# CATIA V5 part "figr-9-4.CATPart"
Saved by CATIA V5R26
Part number: Part1
Bounding box of the stored display mesh (mm): x -71.324 to 69.61, y -139.735 to 0, z 0 to 45
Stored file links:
  D:\_Deepak\CATIA\CATIA V5-6R2016_Deepak\Resources\Part files\Partfiles\c09_catia_v5_6r2016_prt\figr-9-4.CATPart
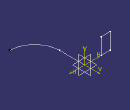
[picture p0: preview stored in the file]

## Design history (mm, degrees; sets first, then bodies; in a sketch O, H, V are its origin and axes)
Body1 (main body)
  Sketch1 on xy-plane, origin (0, 0, 0), H (1, 0, 0), V (0, 1, 0)
    line L1 (0, 0) -> (0, -70.1255)
    arc A1 centre (69.6095, -70.1255) radius 69.6095 from (0, -70.1255) to (69.6095, -139.7351) ccw
    vertical: L1 V
    tangency: A1 L1
  Sketch2 on zx-plane, origin (0, 0, 0), H (-1, 0, 0), V (0, 0, 1)
    point P1 (46.3244, 0)
    line L1 (46.3244, 0) -> (71.3244, 0)
    line L2 (71.3244, 0) -> (71.3244, 45)
    line L3 (71.3244, 45) -> (46.3244, 45)
    line L4 (46.3244, 45) -> (46.3244, 0)
    length L3 = 25
    length L2 = 45
    coincidence: P1 H
    horizontal: L1 H, L3 H
    vertical: L2 V, L4 V
  Rib1: profile Sketch2, centre curve Sketch1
